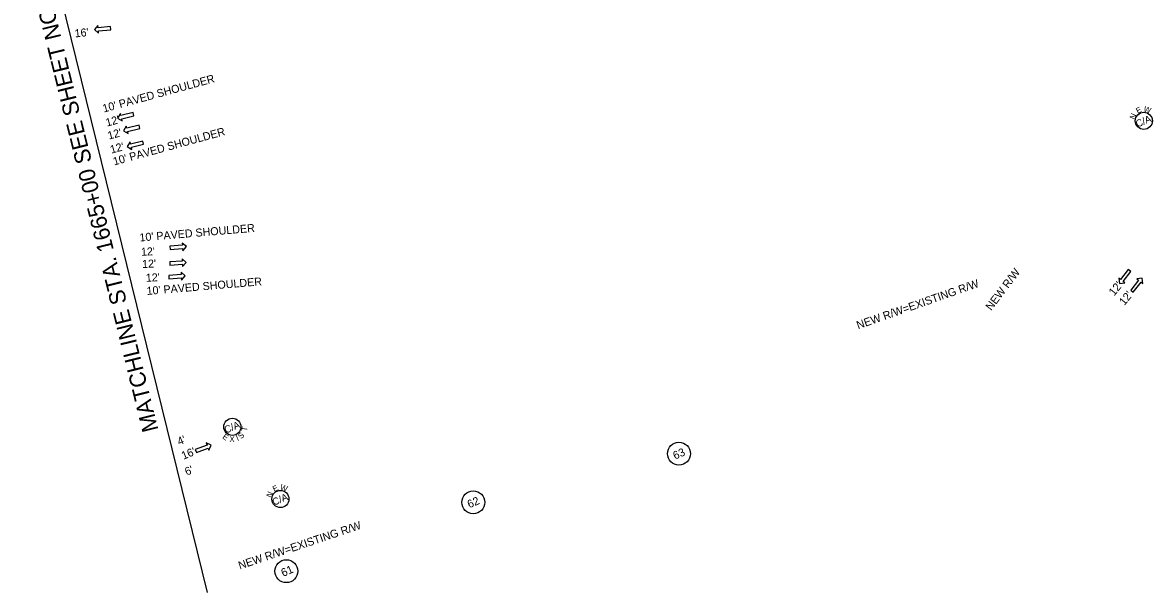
# Model space of a CAD drawing. Extents: x 1813391 to 1815007, y 1189909 to 1191222.
# Drawn here: x 1813391 to 1814379, y 1189909 to 1190407 of the extents above; entities that cross this region are included whole.
import ezdxf

# ---------------------------------------------------------------- set-up
doc = ezdxf.new("R2010")
doc.units = 0
for name, color, linetype in [('RD_EX_DV_Prop_txCode', 7, 'Continuous'), ('RD_EX_DV_TX_Prop', 7, 'Continuous'), ('RD_PD_Final_LnLine', 7, 'Continuous'), ('RD_PD_Final_TX', 7, 'Continuous'), ('RD_PD_RW_TX', 7, 'Continuous'), ('RD_SHT_MatchLine', 7, 'Continuous'), ('RD_SHT_TX', 7, 'Continuous'), ('RD_Sketch10', 7, 'Continuous'), ('RD_Sketch8', 7, 'Continuous')]:
    doc.layers.add(name, color=color, linetype=linetype)

# ---------------------------------------------------------------- blocks, each defined once
blk = doc.blocks.new('SARRW2')
at = {"layer": 'RD_PD_Final_LnLine'}
blk.add_lwpolyline([(-12, 1.2), (-12, -1.2), (-2.83, -1.2), (-2.83, -2.83), (0, 0), (-2.83, 2.83), (-2.83, 1.2)], close=True, dxfattribs=at)

msp = doc.modelspace()

# ---------------------------------------------------------------- linework, layer by layer
at = {"layer": 'RD_EX_DV_TX_Prop'}
for centre in [(1813964.79, 1190030.08), (1813784.92, 1189987.5), (1813621.42, 1189927.3)]:
    msp.add_circle(centre, 10, dxfattribs=at)
at = {"layer": 'RD_SHT_MatchLine'}
msp.add_line((1813390.76, 1190565.47), (1813552.12, 1189908.75), dxfattribs=at)
at = {"layer": 'RD_Sketch10'}
for centre in [(1814371.39, 1190321.18), (1813616.25, 1189990.4)]:
    msp.add_circle(centre, 7.5, dxfattribs=at)
at = {"layer": 'RD_Sketch8'}
msp.add_circle((1813574.24, 1190053.54), 7.5, dxfattribs=at)

# ---------------------------------------------------------------- block references
at = {"layer": 'RD_PD_Final_LnLine'}
for p, xscale, yscale, rotation in [((1813453.51, 1190400.93), 1.2000000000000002, 1.2000000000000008, -174.8585307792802), ((1813473.86, 1190323.58), 1.2, 1.2000000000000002, -166.176346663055), ((1813478.96, 1190312.48), 1.2, 1.2000000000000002, -166.176346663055), ((1813482.3, 1190298.61), 1.2, 1.2000000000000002, -166.176346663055), ((1813533.97, 1190211.17), 1.1999999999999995, 1.1999999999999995, 4.019645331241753), ((1813533.87, 1190197.36), 1.1999999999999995, 1.1999999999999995, 4.019645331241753), ((1813533, 1190185.55), 1.1999999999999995, 1.1999999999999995, 4.019645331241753), ((1814350.02, 1190178.95), 1.1999999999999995, 1.2000000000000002, -128.01889070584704), ((1814369.92, 1190183.62), 1.1999999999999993, 1.2, 51.98110929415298), ((1813555.73, 1190037.46), 1.1999999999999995, 1.1999999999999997, 20.17460262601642)]:
    msp.add_blockref('SARRW2', p, dxfattribs=dict(at, xscale=xscale, yscale=yscale, rotation=rotation))

# ---------------------------------------------------------------- texts
at = {"layer": 'RD_EX_DV_Prop_txCode'}
for s, p in [('63', (1813961.42, 1190024.77)), ('62', (1813781.59, 1189982.21)), ('61', (1813618.68, 1189922.27))]:
    msp.add_text(s, height=7, rotation=23.7538, dxfattribs=at).set_placement(p)
at = {"layer": 'RD_PD_Final_TX'}
for s, rotation, p in [("16'", 6.06532, (1813436.65, 1190394.1)), ("10' PAVED SHOULDER", 15.32936, (1813461.78, 1190328.39)), ("12'", 15.26767, (1813464.47, 1190316.08)), ("12'", 15.26767, (1813466.17, 1190304.68)), ("10' PAVED SHOULDER", 15.32936, (1813470.91, 1190282.14)), ("12'", 15.26767, (1813468.38, 1190292.46)), ("10' PAVED SHOULDER", 4.83238, (1813493.29, 1190215.63)), ("12'", 2.79074, (1813494.45, 1190203.1)), ("12'", 2.79074, (1813495.42, 1190192.42)), ("12'", 2.79074, (1813498.7, 1190180.38)), ("10' PAVED SHOULDER", 4.83238, (1813499.53, 1190168.86)), ("12'", 50.75791, (1814345.45, 1190167.6)), ("12'", 50.75791, (1814354.41, 1190159.24)), ("4'", 22.56659, (1813527.73, 1190037.17)), ("16'", 22.56659, (1813531.41, 1190024.73)), ("6'", 22.56659, (1813534.33, 1190010.8))]:
    msp.add_text(s, height=7, rotation=rotation, dxfattribs=at).set_placement(p)
at = {"layer": 'RD_PD_RW_TX'}
for s, rotation, p in [('NEW R/W', 52.7636, (1814237.86, 1190154.77)), ('NEW R/W=EXISTING R/W', 19.34666, (1814121.56, 1190138.84)), ('NEW R/W=EXISTING R/W', 18.56849, (1813580.78, 1189928.73))]:
    msp.add_text(s, height=7, rotation=rotation, dxfattribs=at).set_placement(p)
at = {"layer": 'RD_SHT_TX'}
msp.add_text('MATCHLINE STA. 1665+00 SEE SHEET NO. SN54', height=14.1726, rotation=103.90674, dxfattribs=at).set_placement((1813509.65, 1190050.94))
at = {"layer": 'RD_Sketch10'}
for s, height, rotation, p in [('E', 5, 26.89964, (1814366.06, 1190327.31)), ('W', 5, 341.8692, (1814370.76, 1190329.53)), ('N', 5, 67.43636, (1814363.34, 1190321.98)), ('C/A', 6.25, 22.56659, (1814365.8, 1190315.3)), ('N', 5, 67.43636, (1813608.2, 1189991.21)), ('E', 5, 26.89964, (1813610.92, 1189996.53)), ('W', 5, 341.8692, (1813615.61, 1189998.75)), ('C/A', 6.25, 22.56659, (1813610.66, 1189984.53))]:
    msp.add_text(s, height=height, rotation=rotation, dxfattribs=at).set_placement(p)
at = {"layer": 'RD_Sketch8'}
for s, height, rotation, p in [('C/A', 6.25, 22.56659, (1813568.65, 1190047.66)), ('E', 5, 325.77783, (1813565.07, 1190043.75)), ('I', 5, 22.3672, (1813578.71, 1190041.05)), ('S', 5, 44.35903, (1813582.02, 1190042.61)), ('T', 5, 80.75173, (1813586.99, 1190049.41)), ('X', 5, 358.2072, (1813571.65, 1190040.36))]:
    msp.add_text(s, height=height, rotation=rotation, dxfattribs=at).set_placement(p)

doc.saveas('drawing.dxf')
